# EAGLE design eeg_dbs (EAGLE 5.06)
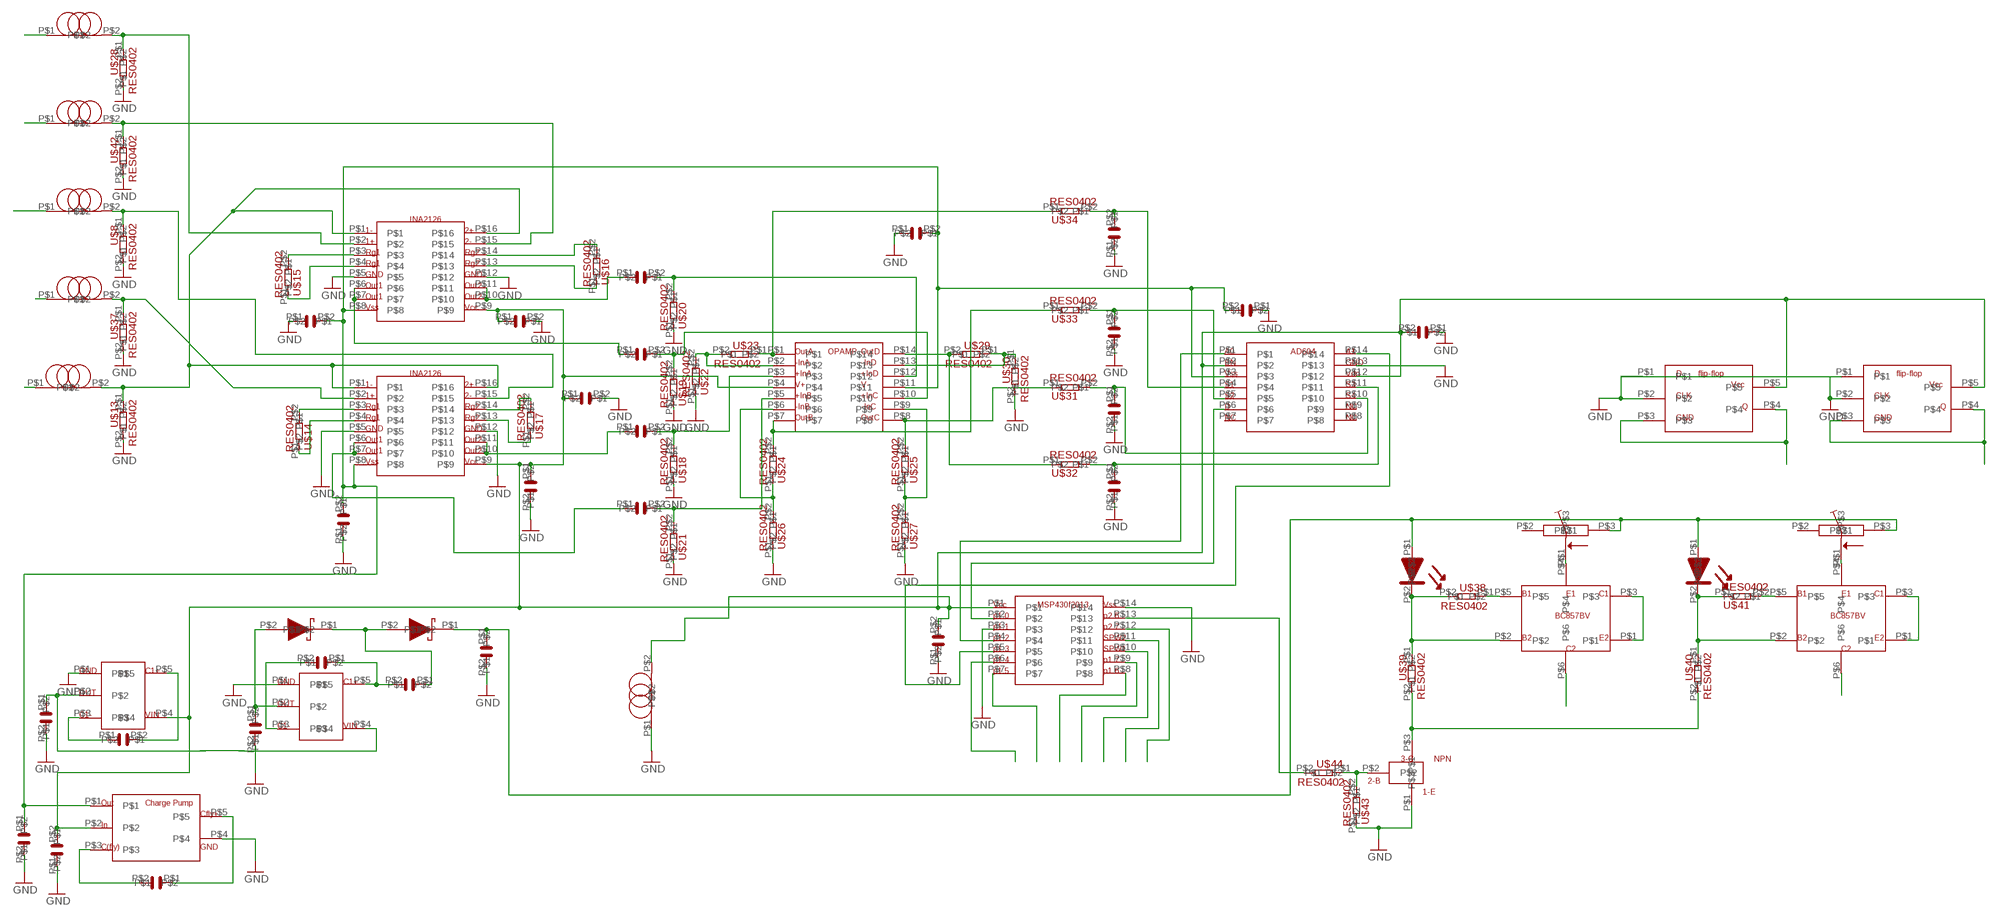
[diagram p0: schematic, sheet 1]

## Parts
U$1  BC857BV  [SOT-666]
U$2  BC857BV  [SOT-666]
U$5  FLIPFLOP  [SC70-5]
U$6  INSTAMP  [SOIC-16]
U$7  INSTAMP  [SOIC-16]
U$8  RES0402  [0402]
U$9  MSP430F2013  [TSSOP-14]
U$10  MULTIPLEXER  [TSSOP-14]
U$11  NPN  [SOT-523]
U$12  OPAMP  [TSSOP-14]
U$13  RES0402  [0402]
U$14  RES0402  [0402]
U$15  RES0402  [0402]
U$16  RES0402  [0402]
U$17  RES0402  [0402]
U$18  RES0402  [0402]
U$19  RES0402  [0402]
U$20  RES0402  [0402]
U$21  RES0402  [0402]
U$22  RES0402  [0402]
U$23  RES0402  [0402]
U$24  RES0402  [0402]
U$25  RES0402  [0402]
U$26  RES0402  [0402]
U$27  RES0402  [0402]
U$28  RES0402  [0402]
U$29  RES0402  [0402]
U$30  RES0402  [0402]
U$31  RES0402  [0402]
U$32  RES0402  [0402]
U$33  RES0402  [0402]
U$34  RES0402  [0402]
U$35  CAP0402  [0402]
U$36  CAP0402  [0402]
U$37  RES0402  [0402]
U$38  RES0402  [0402]
U$39  RES0402  [0402]
U$40  RES0402  [0402]
U$41  RES0402  [0402]
U$42  RES0402  [0402]
U$43  RES0402  [0402]
U$44  RES0402  [0402]
U$45  CAP0402  [0402]
U$46  CAP0402  [0402]
U$47  CAP0402  [0402]
U$48  CHARGEPUMP  [SOT-23]
U$49  CAP0402  [0402]
U$50  MAX1683  [SOT-23]
U$51  MAX1683  [SOT-23]
U$52  IND0603  [0603]
U$53  CAP0402  [0402]
U$54  CAP0402  [0402]
U$55  CAP0402  [0402]
U$56  CAP0402  [0402]
U$57  CAP0402  [0402]
U$58  CAP0402  [0402]
U$59  CAP0402  [0402]
U$60  CAP0402  [0402]
U$61  CAP0402  [0402]
U$62  CAP0402  [0402]
U$63  CAP0402  [0402]
U$64  CAP0402  [0402]
U$65  CAP0402  [0402]
U$66  CAP0402  [0402]
U$67  CAP0402  [0402]
U$68  CAP0402  [0402]
U$69  LED  [0402]
U$70  LED  [0402]
U$72  CAP0402  [0402]
U$73  CAP0402  [0402]
U$74  DIODE  [S0D-923]
U$75  DIODE  [S0D-923]
U$76  CAP0402  [0402]
U$77  CAP0402  [0402]
U$78  IND0603  [0603]
U$79  IND0603  [0603]
U$80  IND0603  [0603]
U$81  IND0603  [0603]
U$82  IND0603  [0603]
U$83  FLIPFLOP  [SC70-5]
U$84  TRIMMER2MM  [TRIM-MC]
U$85  TRIMMER2MM  [TRIM-MC]

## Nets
GND: U$5.P$1 U$5.P$2 U$6.P$5 U$6.P$12 U$7.P$5 U$7.P$12 U$8.P$2 U$9.P$3 U$9.P$14 U$10.P$13 U$11.P$1 U$13.P$2 U$18.P$1 U$19.P$1 U$20.P$1 U$21.P$1 U$22.P$1 U$26.P$1 U$27.P$1 U$28.P$2 U$30.P$2 U$36.P$1 U$37.P$2 U$42.P$2 U$43.P$1 U$45.P$1 U$46.P$2 U$47.P$1 U$48.P$4 U$49.P$2 U$50.P$1 U$51.P$1 U$52.P$1 U$57.P$1 U$58.P$1 U$59.P$1 U$60.P$1 U$61.P$2 U$62.P$2 U$63.P$2 U$64.P$1 U$65.P$2 U$66.P$2 U$68.P$2 U$73.P$2 U$77.P$2 U$83.P$1 U$83.P$2
N$1: U$6.P$1 U$6.P$16 U$7.P$1 U$7.P$16 U$13.P$1 U$78.P$2
N$2: U$6.P$2 U$28.P$1 U$81.P$2
N$3: U$5.P$3 U$5.P$4
N$4: U$83.P$3 U$83.P$4
N$9: U$7.P$3 U$14.P$2
N$10: U$7.P$4 U$14.P$1
N$11: U$7.P$13 U$17.P$1
N$12: U$7.P$14 U$17.P$2
N$13: U$6.P$3 U$15.P$2
N$14: U$7.P$10 U$7.P$11 U$55.P$1
N$17: U$6.P$14 U$16.P$2
N$19: U$6.P$4 U$15.P$1
N$20: U$12.P$10 U$19.P$2 U$54.P$2
N$21: U$6.P$13 U$16.P$1
N$22: U$5.P$5 U$6.P$9 U$7.P$9 U$9.P$1 U$10.P$2 U$10.P$12 U$12.P$4 U$36.P$2 U$46.P$1 U$48.P$2 U$49.P$1 U$50.P$4 U$52.P$2 U$57.P$2 U$64.P$2 U$68.P$1 U$83.P$5
N$24: U$81.P$1
N$25: U$6.P$10 U$6.P$11 U$53.P$1
N$26: U$82.P$1
N$27: U$6.P$6 U$6.P$7 U$54.P$1
N$28: U$12.P$12 U$20.P$2 U$53.P$2
N$29: U$12.P$1 U$23.P$1 U$34.P$1
N$30: U$35.P$2 U$48.P$3
N$31: U$12.P$5 U$21.P$2 U$56.P$2
N$32: U$7.P$6 U$7.P$7 U$56.P$1
N$33: U$12.P$2 U$22.P$2 U$23.P$2
N$34: U$12.P$7 U$24.P$2 U$33.P$1
N$35: U$12.P$6 U$24.P$1 U$26.P$2
N$36: U$10.P$10 U$31.P$2 U$62.P$1
N$37: U$12.P$8 U$25.P$2 U$31.P$1
N$38: U$12.P$9 U$25.P$1 U$27.P$2
N$39: U$12.P$14 U$29.P$2 U$32.P$1
N$40: U$12.P$13 U$29.P$1 U$30.P$1
N$42: U$6.P$15 U$42.P$1 U$80.P$2
N$43: U$10.P$11 U$32.P$2 U$63.P$1
N$44: U$9.P$2 U$10.P$6
N$45: U$9.P$4 U$10.P$1
N$46: U$9.P$5 U$10.P$14
N$47: U$12.P$3 U$18.P$2 U$55.P$2
N$48: U$35.P$1 U$48.P$5
N$49: U$9.P$6
N$50: U$9.P$7
N$51: U$9.P$8
N$52: U$9.P$9
N$53: U$9.P$10
N$54: U$9.P$11
N$55: U$9.P$12
N$56: U$50.P$3 U$67.P$1
N$57: U$50.P$5 U$67.P$2
N$58: U$2.P$2 U$38.P$2 U$39.P$1 U$69.P$2
N$59: U$2.P$5 U$38.P$1
N$60: U$2.P$4 U$84.P$1
N$61: U$11.P$3 U$39.P$2 U$40.P$2
N$62: U$2.P$6
N$63: U$2.P$1 U$2.P$3
N$64: U$1.P$4 U$85.P$1
N$65: U$1.P$2 U$40.P$1 U$41.P$1 U$70.P$2
N$66: U$1.P$5 U$41.P$2
N$67: U$1.P$6
N$68: U$1.P$1 U$1.P$3
N$69: U$50.P$2 U$51.P$4 U$66.P$1
N$70: U$11.P$2 U$43.P$2 U$44.P$1
N$71: U$51.P$3 U$72.P$2
N$72: U$9.P$13 U$44.P$2
N$73: U$6.P$8 U$7.P$8 U$10.P$3 U$12.P$11 U$45.P$2 U$47.P$2 U$48.P$1 U$58.P$2 U$60.P$2 U$65.P$1
N$74: U$51.P$5 U$72.P$1 U$76.P$2
N$75: U$51.P$2 U$73.P$1 U$74.P$2
N$76: U$74.P$1 U$75.P$2 U$76.P$1
N$77: U$69.P$1 U$70.P$1 U$75.P$1 U$77.P$1 U$84.P$3 U$85.P$3
N$78: U$10.P$4 U$34.P$2 U$59.P$2
N$82: U$10.P$5 U$33.P$2 U$61.P$1
N$83: U$7.P$15 U$8.P$1 U$82.P$2
N$84: U$80.P$1
N$85: U$7.P$2 U$37.P$1 U$79.P$2
N$86: U$79.P$1
N$89: U$78.P$1
Unconnected: U$10.P$7 U$10.P$8 U$10.P$9 U$84.P$2 U$85.P$2

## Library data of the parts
U$1 U$2 = my project parts:BC857BV
U$5 U$83 = my project parts:FLIPFLOP
U$6 U$7 = my project parts:INSTAMP
U$8 U$13-U$34 U$37-U$44 = my project parts:RES0402
U$9 = my project parts:MSP430F2013
U$10 = my project parts:MULTIPLEXER
U$11 = my project parts:NPN
U$12 = my project parts:OPAMP
U$35 U$36 U$45-U$47 U$49 U$53-U$68 U$72 U$73 U$76 U$77 = my project parts:CAP0402
U$48 = my project parts:CHARGEPUMP
U$50 U$51 = my project parts:MAX1683
U$52 U$78-U$82 = my project parts:IND0603
U$69 U$70 = my project parts:LED
U$74 U$75 = my project parts:DIODE
U$84 U$85 = my project parts:TRIMMER2MM

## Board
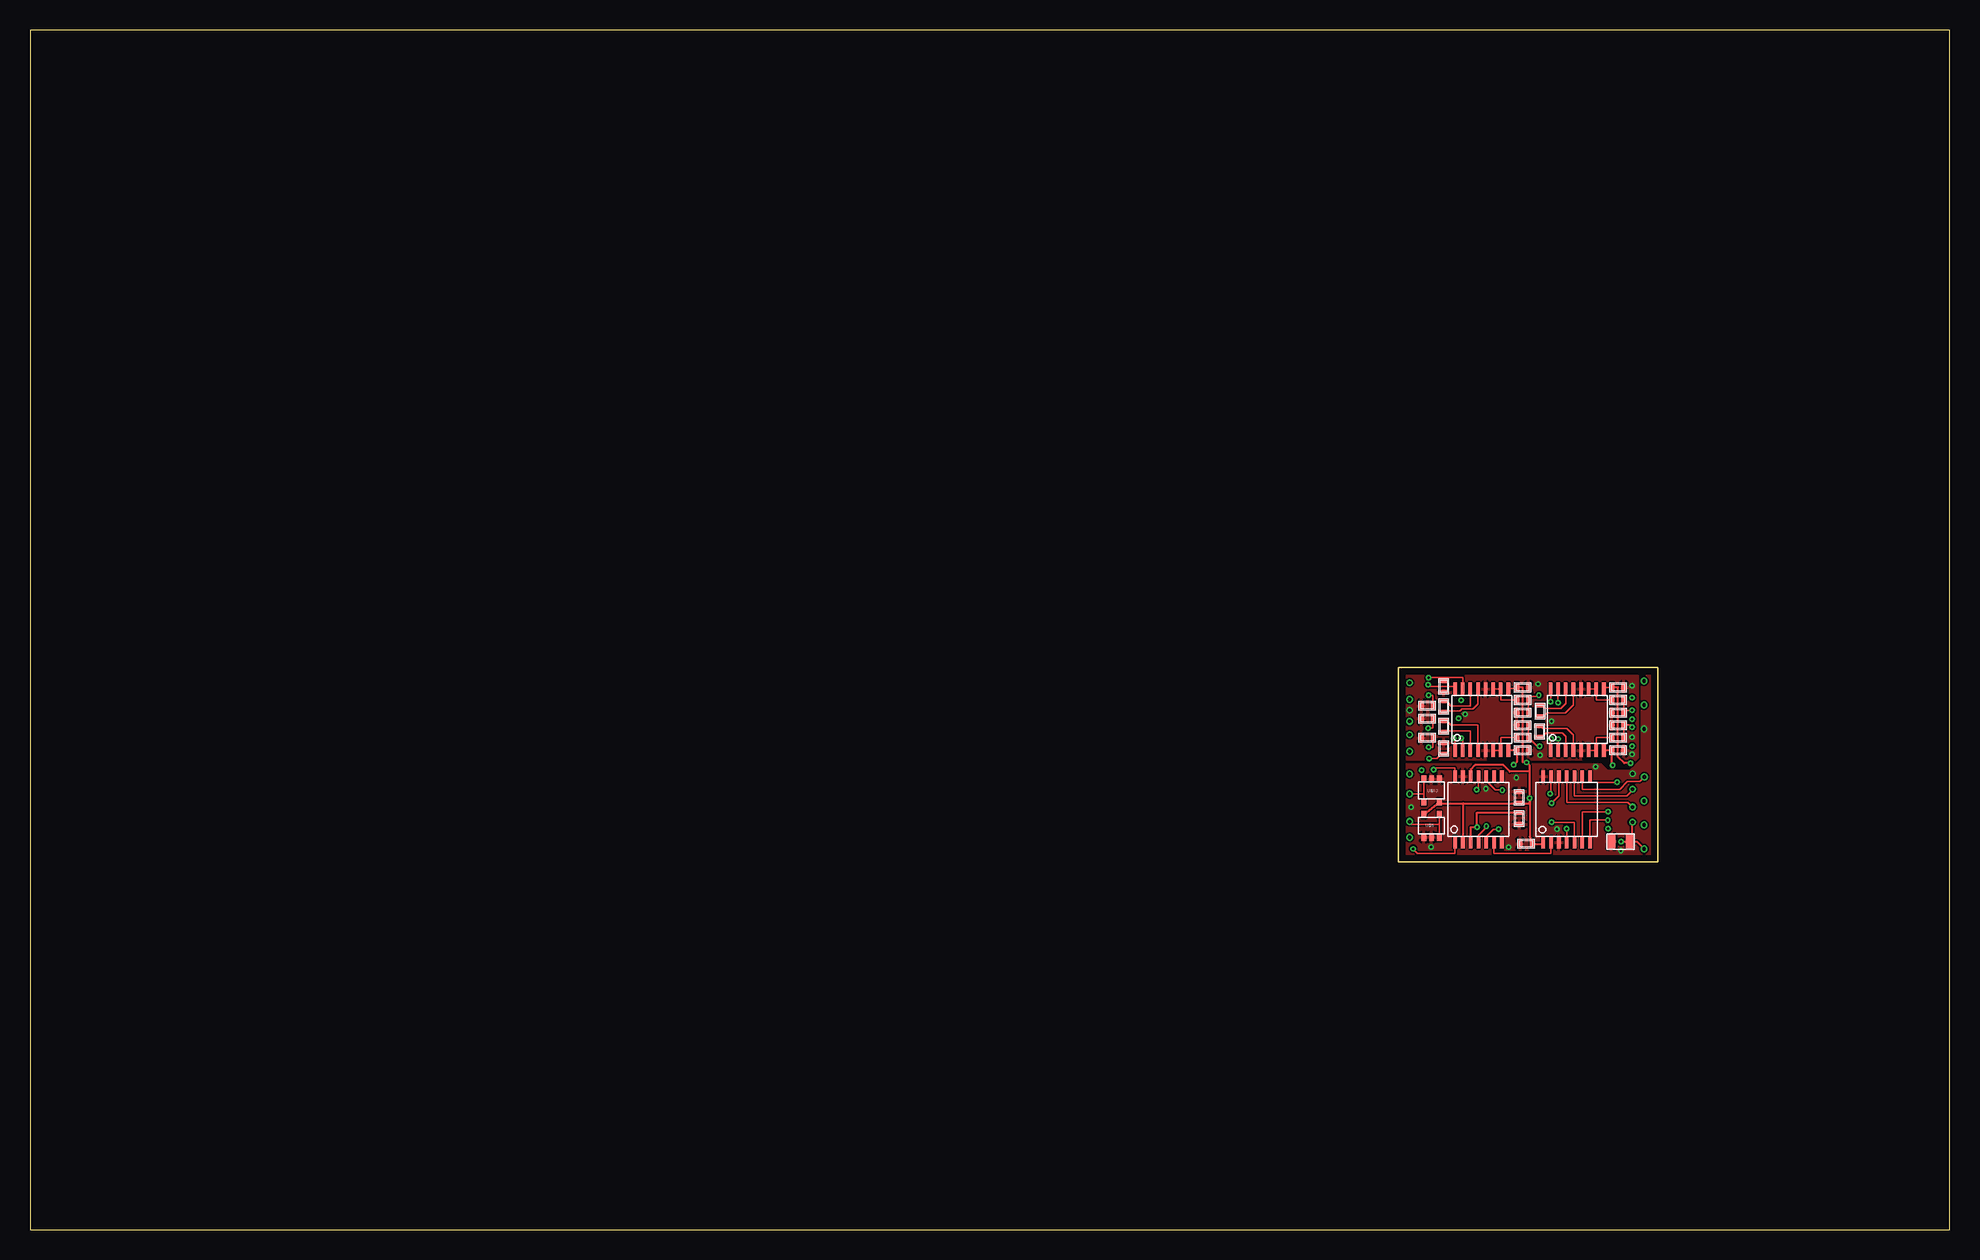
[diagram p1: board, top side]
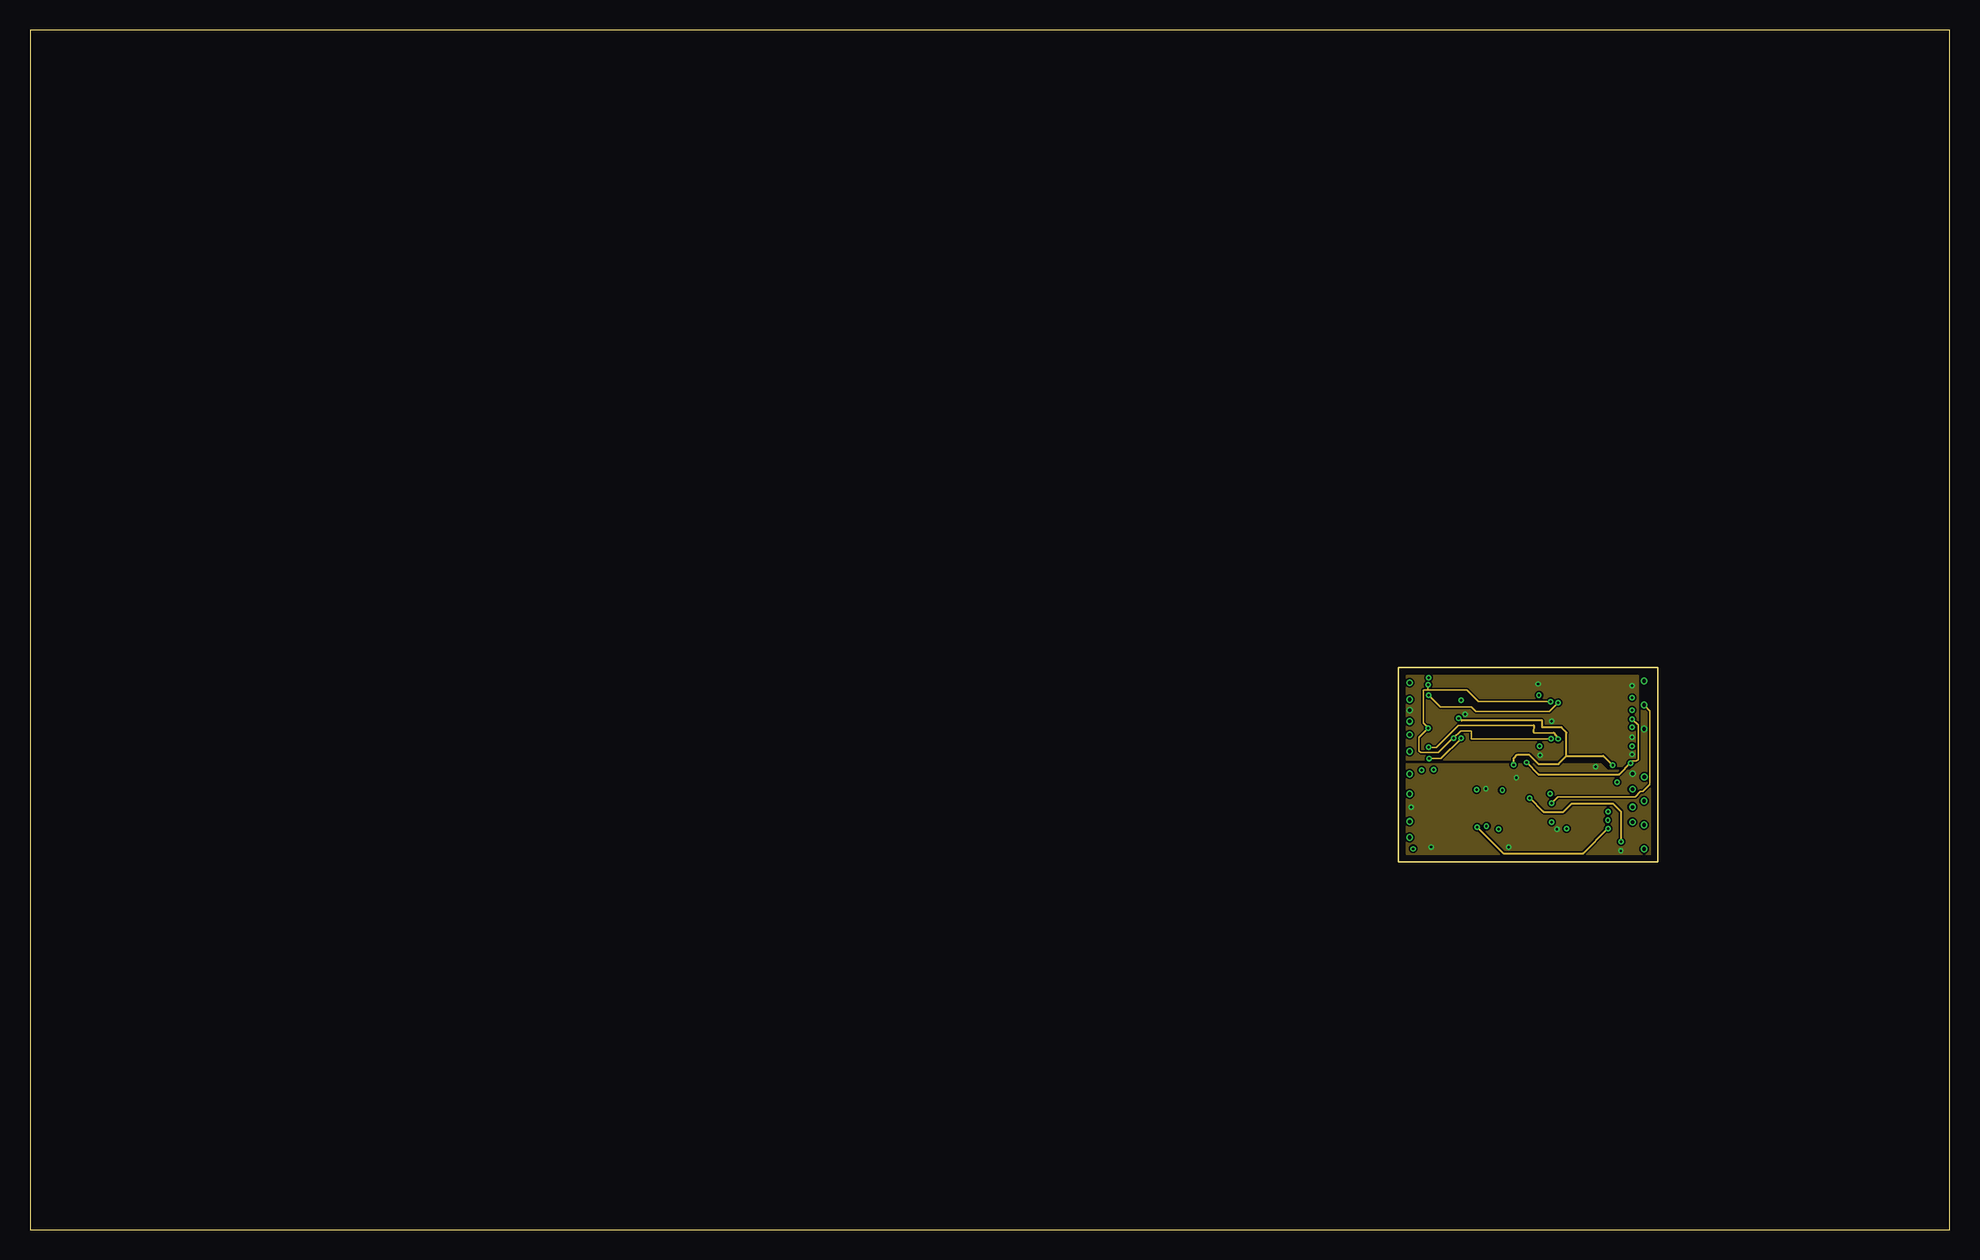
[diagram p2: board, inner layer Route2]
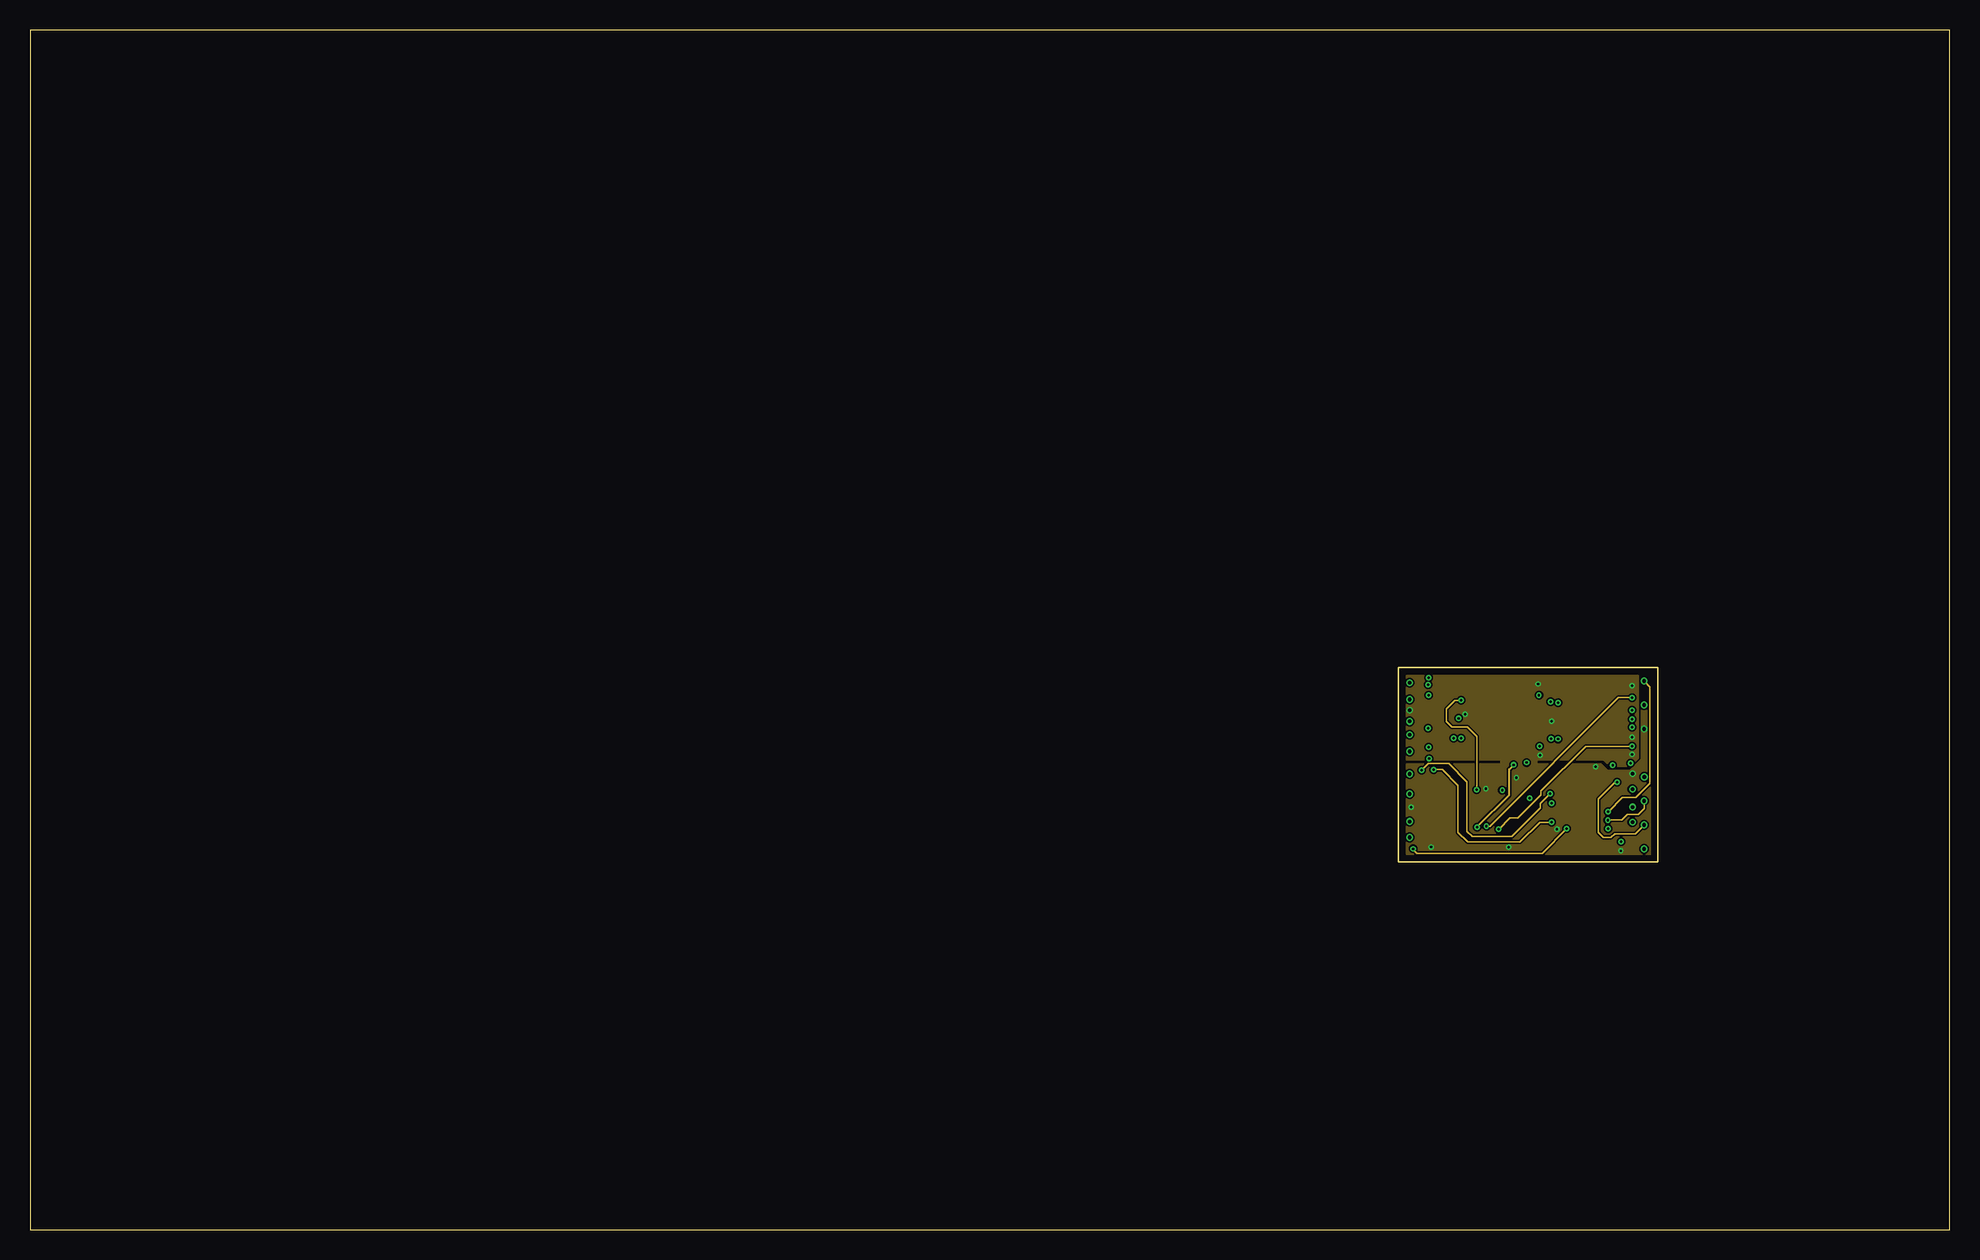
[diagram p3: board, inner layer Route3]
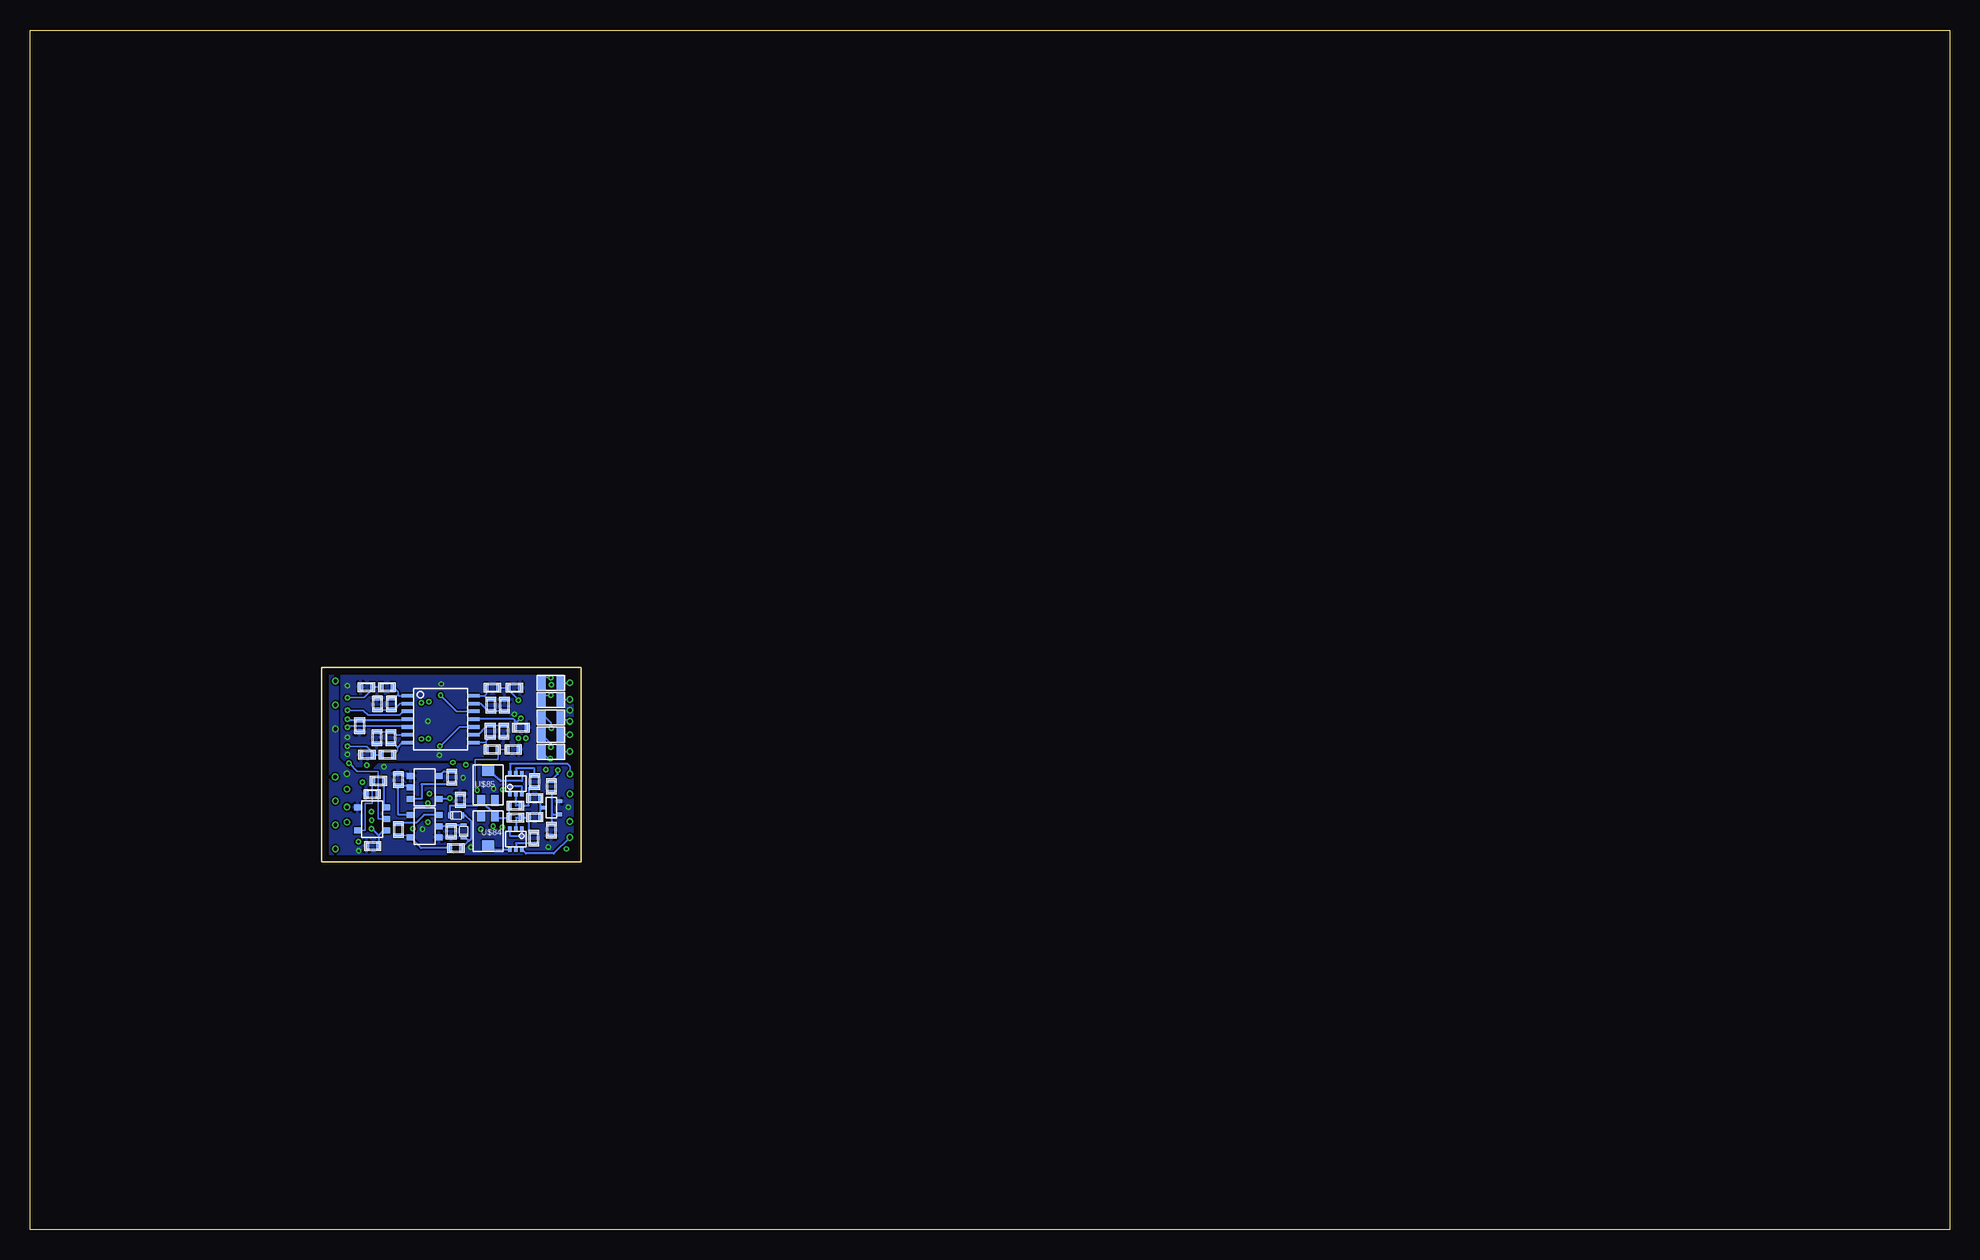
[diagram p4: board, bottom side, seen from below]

Size 160 x 100 mm. Coordinates in mm from the lower left corner, seen from the top.
Outline: 0,0 160,0 160,100 0,100 0,0
Outline: 135.7,46.85 135.7,30.63 114.07,30.63 114.07,46.85 135.7,46.85
Copper layers (1+2*3+16): Top 0.035mm / dielectric 0.38mm / Route2 0.035mm / dielectric 0.71mm / Route3 0.035mm / dielectric 0.38mm / Bottom 0.035mm
Design rules "default *": minimum track width 0.125mm, minimum drill 0.2mm, track to track 5mil, track to pad 6mil, pad to pad 6mil, via to via 5mil, smd to smd 6mil, copper to edge 0.5mm, drill to drill 8mil, minimum pad ring 10mil, minimum via ring 5mil, stop-mask expansion 3mil, vias tented up to drill 8mil, thermal gap 0.2mm

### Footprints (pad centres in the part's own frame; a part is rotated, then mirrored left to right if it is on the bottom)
SOT-666 = smd 0.3 x 0.4: P$1 -0.5,-0.85; P$2 0,-0.85; P$3 0.5,-0.85; P$4 0.5,0.85; P$5 0,0.85; P$6 -0.5,0.85
SC70-5 = smd 0.4 x 0.6: P$1 -0.65,-0.95; P$2 0,-0.95; P$3 0.65,-0.95; P$4 0.65,0.95; P$5 -0.65,0.95
SOIC-16 = smd 0.3 x 1.1: P$1 -2.223,-2.55; P$2 -1.587,-2.55; P$3 -0.953,-2.55; P$4 -0.318,-2.55; P$5 0.318,-2.55; P$6 0.953,-2.55; P$7 1.587,-2.55; P$8 2.223,-2.55; P$9 2.223,2.55; P$10 1.587,2.55; P$11 0.953,2.55; P$12 0.318,2.55; P$13 -0.318,2.55; P$14 -0.953,2.55; P$15 -1.587,2.55; P$16 -2.223,2.55
0402 = smd 0.381 x 0.8: P$1 -0.49,0; P$2 0.49,0
TSSOP-14 = smd 0.3 x 1: P$1 -1.95,-2.75; P$2 -1.3,-2.75; P$3 -0.65,-2.75; P$4 0,-2.75; P$5 0.65,-2.75; P$6 1.3,-2.75; P$7 1.95,-2.75; P$8 1.95,2.75; P$9 1.3,2.75; P$10 0.65,2.75; P$11 0,2.75; P$12 -0.65,2.75; P$13 -1.3,2.75; P$14 -1.95,2.75
SOT-523 = smd 0.3 x 0.45: P$1 0.55,-0.65; P$2 -0.55,-0.65; P$3 0,0.65
SOT-23 = smd 0.5 x 0.625: P$1 -0.95,-1.188; P$2 0,-1.188; P$3 0.95,-1.188; P$4 0.95,1.188; P$5 -0.95,1.188
0603 = smd 0.629 x 1.138: P$1 -0.764,0; P$2 0.764,0
S0D-923 = smd 0.25 x 0.5: P$1 -0.53,0; P$2 0.53,0
TRIM-MC = smd 1 x 0.9: P$1 0,1.25 | smd 0.65 x 0.9: P$2 0.575,-1.25; P$3 -0.575,-1.25

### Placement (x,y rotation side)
U$1  119.49,37.17 0 bottom
U$2  119.49,32.54 180 bottom
U$5  116.83,33.66 0 top
U$6  121.01,42.5 0 top
U$7  128.96,42.5 0 top
U$8  116.47,43.66 180 top
U$9  128.09,35.01 0 top
U$10  120.74,35.03 0 top
U$11  116.53,35.15 90 bottom
U$12  125.79,42.55 270 bottom
U$13  116.47,42.59 180 top
U$14  125.85,41.52 270 top
U$15  117.85,41.95 270 top
U$16  117.85,43.6 90 top
U$17  125.86,43.22 90 top
U$18  132.37,43.09 0 top
U$19  124.42,42.05 0 top
U$20  124.42,43.09 0 top
U$21  132.37,42.05 0 top
U$22  131.05,43.82 270 bottom
U$23  129.86,43.82 270 bottom
U$24  129.93,41 270 bottom
U$25  121.64,41.54 270 bottom
U$26  131.09,41 90 bottom
U$27  120.51,41.54 90 bottom
U$28  117.85,40.11 90 top
U$29  121.59,43.7 90 bottom
U$30  120.45,43.7 90 bottom
U$31  121.48,40.02 0 bottom
U$32  121.46,45.15 0 bottom
U$33  130.21,39.58 180 bottom
U$34  130.24,45.22 180 bottom
U$35  130.95,37.39 0 bottom
U$36  131.48,36.31 0 bottom
U$37  116.47,41 180 top
U$38  118,32.63 90 bottom
U$39  117.93,34.36 0 bottom
U$40  117.93,35.95 0 bottom
U$41  117.94,37.33 90 bottom
U$42  117.85,45.28 270 top
U$43  116.55,33.3 90 bottom
U$44  116.55,36.94 90 bottom
U$45  124.42,39.95 180 top
U$46  124.42,45.19 0 top
U$47  132.37,39.95 180 top
U$48  131.49,34.22 90 bottom
U$49  132.37,45.19 0 top
U$50  127.09,36.86 270 bottom
U$51  127.09,33.62 90 bottom
U$52  132.59,32.34 0 top
U$53  124.42,44.14 0 top
U$54  124.42,41 0 top
U$55  132.37,44.14 0 top
U$56  132.37,41 0 top
U$57  124.7,32.16 0 top
U$58  119.08,41.85 180 bottom
U$59  131.95,45.22 0 bottom
U$60  124.13,34.26 90 top
U$61  131.91,39.58 180 bottom
U$62  119.73,40.02 0 bottom
U$63  119.63,45.15 0 bottom
U$64  124.13,36.02 270 top
U$65  131.43,31.96 180 bottom
U$66  129.3,37.49 90 bottom
U$67  124.84,37.71 90 bottom
U$68  132.52,41.99 270 bottom
U$69  119.56,34.32 0 bottom
U$70  119.56,35.35 0 bottom
U$72  129.3,33.33 90 bottom
U$73  124.89,33.19 270 bottom
U$74  123.86,33.2 90 bottom
U$75  124.48,34.52 0 bottom
U$76  124.51,31.8 180 bottom
U$77  124.13,35.81 90 bottom
U$78  116.57,42.7 180 bottom
U$79  116.57,41.26 180 bottom
U$80  116.57,45.58 180 bottom
U$81  116.57,39.81 180 bottom
U$82  116.57,44.15 180 bottom
U$83  116.83,36.6 180 top
U$84  121.82,33.23 180 bottom
U$85  121.82,37.03 0 bottom

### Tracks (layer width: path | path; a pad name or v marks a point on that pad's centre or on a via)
GND  (via drill 0.2, 0.3)
  other vias: 119.64,42.97 126.84,42.38 133.56,39.61 133.56,45.34 125.87,39.53 125.71,45.48 133.56,41.04 134.54,41.73 127.27,33.38 121.35,36.74 123.9,37.66 133.57,37.99 115.13,35.2 114.99,43.28 123.26,31.86 116.79,31.89 130.5,38.57 132.61,31.57
  pour Top: 135.16,31.29 114.74,31.29 114.74,38.85 130.94,38.81 131.49,38.26 133.41,38.26 134.33,39.18 134.33,46.19 135.16,46.19
  pour Bottom: 135.16,31.29 114.74,31.29 114.74,38.81 130.94,38.81 131.49,38.26 133.41,38.26 134.33,39.18 134.33,46.19 135.16,46.19
  pour Route2: 114.74,46.19 134.04,46.19 134.04,39.33 133.3,38.59 131.75,38.59 131.2,39.14 114.74,39.14
  pour Route2: 135.16,31.29 114.74,31.29 114.74,38.84 130.94,38.81 131.49,38.26 133.41,38.26 134.33,39.18 134.33,46.19 135.16,46.19
  pour Top: 114.74,46.19 134.04,46.19 134.04,39.33 133.3,38.59 131.75,38.59 131.2,39.14 114.74,39.14
  pour Route3: 135.16,31.29 114.74,31.29 114.74,38.83 122.6,38.81 122.6,39.14 114.74,39.14 114.74,46.19 134.04,46.19 134.04,39.33 133.3,38.59 131.75,38.59 131.2,39.14 125.6,39.14 125.6,38.81 130.94,38.81 131.49,38.26 133.41,38.26 134.33,39.18 134.33,46.19 135.16,46.19
  pour Bottom: 134.04,46.19 134.04,39.33 133.3,38.59 131.75,38.59 131.2,39.14 117.9,39.14 117.85,46.19
  pour Bottom: 114.74,46.19 117.08,46.19 117.08,39.14 114.74,39.14
N$1  (via drill 0.2)
  Top 0.125: 118.76,45.27 U$6.P$16 118.79,45.28 116.73,45.28 v116.53,45.41 | U$13.P$1 116.96,41.79 v116.56,41.79 | v118.67,40.96 118.79,40.84 U$6.P$1 | v126.75,44 126.75,45.04 U$7.P$16 | v126.79,40.91 126.74,40.86 U$7.P$1
  Route2 0.125: 116.53,44.96 119.78,44.96 120.74,44 v126.75,44 | v126.79,40.91 120.14,40.91 120.14,41.58 119.28,41.58 v118.67,40.96 118.6,40.96 117.39,39.76 115.92,39.76 115.78,39.9 115.78,41.02 116.53,41.77 v116.56,41.79 116.14,42.21 116.14,44.96 116.53,44.96 | 116.53,44.96 v116.53,45.41
  Bottom 0.125: v116.56,41.79 116.56,42.25 117.01,42.7 U$78.P$2
N$2  (via drill 0.2)
  Top 0.125: 117.93,39.49 U$28.P$1 117.62,39.62 117.27,39.27 v116.62,39.27 | 119.5,39.93 119.44,39.93 arc-90 U$6.P$2 119.42,40.83 v119.29,40.96
  Route2 0.125: v119.29,40.96 117.6,39.27 v116.62,39.27
  Bottom 0.125: U$81.P$2 116.81,39.27 v116.62,39.27
N$3  (via drill 0.3)
  Top 0.125: 117.48,33.77 U$5.P$4 | U$5.P$3 117.48,33.77 | v114.99,34.02 115.06,33.77 117.48,33.77
N$4  (via drill 0.3)
  Top 0.125: U$83.P$3 116.18,36.17 | 116.18,36.17 U$83.P$4 | v114.99,36.31 116.18,36.31 116.18,36.17
N$9
  Top 0.125: U$7.P$3 128.01,41.11 127.73,41.39 126.4,41.39 126.04,41.03 U$14.P$2
N$10
  Top 0.125: 126,41.95 125.97,42.07 U$14.P$1 126.08,41.78 128.1,41.78 128.64,41.23 U$7.P$4
N$11
  Top 0.125: 126,42.84 126.02,42.71 125.58,42.78 U$17.P$1 126.1,42.73 126.43,43.06 128,43.06 128.64,43.71 U$7.P$13
  Top 0.15: U$17.P$1 125.53,42.71
N$12
  Top 0.125: U$17.P$2 126.15,43.61 126.31,43.45 127.6,43.45 128.01,43.85 U$7.P$14
N$13
  Top 0.125: U$15.P$2 117.91,41.51 117.57,41.39 117.98,41.56 120.06,41.56 U$6.P$3
N$14
  Top 0.125: U$7.P$11 U$7.P$10 130.55,44.14 U$55.P$1
N$17
  Top 0.125: U$6.P$14 120.06,43.66 118.44,43.66 118.08,44.09 U$16.P$2
N$19
  Top 0.125: U$6.P$4 120.69,42.06 118.44,42.06 118.06,42.44 U$15.P$1
N$20  (via drill 0.2)
  Top 0.125: v125.83,40.28 125.64,40.28 U$54.P$2 U$19.P$2
  Bottom 0.125: U$12.P$10 124.21,41.9 v125.83,40.28
N$21
  Top 0.125: U$16.P$1 117.55,43.23 119.17,43.23 119.34,43.4 120.28,43.4 120.69,43.82 U$6.P$13
N$22  (via drill 0.2, 0.3)
  Top 0.125: U$7.P$9 131.17,45.15 131.21,45.19 U$49.P$1 | U$10.P$12 | 123.17,45.11 123.93,45.11 U$46.P$1
  Top 0.15: 123.17,45.11 U$6.P$9 | U$46.P$1 124.43,45.19 124.43,38.95 124.74,38.95 v124.75,38.94 125.01,38.68 125.01,38.19 | v125.01,35.98 125.01,38.19 | U$49.P$1 132.37,45.19 132.37,39.38 132.88,38.88 v133.41,38.88 | 117.6,35.53 U$64.P$2 125.01,35.53 v125.01,35.98 | 117.6,35.53 U$83.P$5 U$5.P$5 | 117.6,35.53 119.44,35.53 U$10.P$2 | U$9.P$1 126.14,32.16 U$57.P$2 125.01,32.73 v125.01,35.98 | v132.61,32.33 v132.62,32.34 U$52.P$2 | U$52.P$2 133.93,32.34 v134.54,31.73 | v133.57,33.97 133.57,32.55 U$52.P$2 | U$10.P$12 120.09,38.36 120.45,38.71 122.81,38.71 123.33,38.19 125.01,38.19
  Route2 0.125: v133.41,38.88 133.58,39.05 133.91,39.05 134.05,39.19 134.05,42.05 v133.56,42.54
  Route2 0.15: v125.01,35.98 126.17,34.82 127.82,34.82 128.51,35.51 131.96,35.51 132.61,34.85 v132.61,32.33 | v133.41,38.88 132.47,37.94 125.75,37.94 v124.75,38.94
  Bottom 0.125: v133.41,38.88 132.72,38.19 130.96,38.19 130.96,36.34 U$36.P$2 130.99,34.22 U$48.P$2
  Bottom 0.15: U$36.P$2 130.95,36.35 | v133.56,42.54 133.5,42.48 U$68.P$1 128.61,42.48 U$12.P$4 | v125.01,35.98 125.07,35.91 U$50.P$4
N$24  (via drill 0.3)
  Bottom 0.15: U$81.P$1 v114.99,39.85
N$25
  Top 0.125: U$6.P$11 U$6.P$10 122.6,44.14 U$53.P$1
N$26  (via drill 0.3)
  Bottom 0.15: U$82.P$1 v114.99,44.19
N$27
  Top 0.125: U$6.P$6 U$6.P$7 122.6,41 U$54.P$1
N$28  (via drill 0.2)
  Top 0.125: U$20.P$2 U$53.P$2 124.92,44.45 125.68,44.45 v125.77,44.53
  Top 0.15: U$20.P$2 124.82,42.94 | U$53.P$2 124.98,44.04
  Bottom 0.125: U$12.P$12 124.44,43.2 v125.77,44.53
N$29
  Bottom 0.125: 129.33,44.59 129.6,44.31 U$23.P$1 | U$34.P$1 129.33,44.8 129.33,44.59 | U$12.P$1 129.24,44.5 129.33,44.59
N$30
  Bottom 0.15: U$35.P$2 130.46,35.33 arc-90 U$48.P$3
N$31  (via drill 0.2)
  Top 0.125: U$56.P$2 132.88,40.89 132.88,42.03 U$21.P$2 133.39,42.05 v133.56,41.88
  Bottom 0.125: U$12.P$5 128.76,41.98 133.45,41.98 v133.56,41.88
N$32
  Top 0.125: U$7.P$6 U$7.P$7 130.55,41 U$56.P$1
N$33
  Bottom 0.125: U$22.P$2 U$23.P$2 129.65,43.33 129.13,43.85 U$12.P$2
N$34
  Bottom 0.125: 129.72,40.41 U$24.P$2 129.69,40.51 129.37,40.2 | U$33.P$1 129.37,39.93 129.37,40.2 | 129.37,40.2 128.97,40.6 U$12.P$7
N$35
  Bottom 0.125: U$12.P$6 129.44,41.25 129.68,41.49 U$24.P$1 U$26.P$2
N$36  (via drill 0.2)
  Top 0.125: U$10.P$10 121.39,37.4 122.16,36.63 v122.73,36.63
  Bottom 0.125: U$31.P$2 120.9,40.01 | U$31.P$2 120.86,39.96 | U$31.P$2 U$62.P$1 | U$31.P$2 120.99,39.18 122.89,39.18 122.89,36.8 v122.73,36.63
N$37
  Bottom 0.125: U$25.P$2 121.97,40.72 121.97,40.59 | U$31.P$1 121.97,40.59 | U$12.P$8 121.97,40.59
N$38
  Bottom 0.125: U$27.P$2 U$25.P$1 121.81,41.92 121.98,41.92 122.66,41.25 U$12.P$9
N$39
  Bottom 0.125: 121.85,44.31 U$29.P$2 121.82,44.19 122.12,44.5 | 122.12,44.5 U$12.P$14 | U$32.P$1 121.95,44.67 122.12,44.5
N$40
  Bottom 0.125: U$12.P$13 122.44,43.85 121.8,43.21 U$29.P$1 U$30.P$1
N$42  (via drill 0.2)
  Top 0.125: v116.59,46.01 117.86,46.01 | 117.86,46.01 119.42,46.01 U$6.P$15 | U$42.P$1 117.86,45.77 117.86,46.01
  Bottom 0.125: v116.59,46.01 117.33,46.01 U$80.P$2
N$43  (via drill 0.2)
  Top 0.125: U$10.P$11 120.74,36.82 v120.58,36.66
  Route3 0.125: v120.58,36.66 120.58,41.1 119.81,41.88 118.52,41.88 118.05,42.35 118.05,43.38 118.78,44.11 v119.28,44.11
  Bottom 0.125: U$32.P$2 U$63.P$1 120.12,45.01 v119.28,44.11
N$44
  Top 0.125: U$10.P$6 122.04,31.36 126.79,31.36 U$9.P$2
N$45  (via drill 0.2)
  Top 0.125: U$10.P$1 118.79,31.36 115.65,31.36 v115.28,31.73 | v128.08,33.42 U$9.P$4
  Route3 0.125: v128.08,33.42 126.06,31.36 115.62,31.36 v115.28,31.73
N$46  (via drill 0.2)
  Top 0.125: U$10.P$14 118.79,38.46 117.11,38.46 v117,38.34 | v126.83,33.95 128.74,33.95 U$9.P$5
  Route3 0.125: v117,38.34 117.72,38.34 119.04,37.03 119.04,33.09 119.84,32.3 124.21,32.3 125.86,33.95 v126.83,33.95
N$47  (via drill 0.2)
  Top 0.125: v133.55,43.28 132.86,43.28 U$18.P$2 U$55.P$2
  Bottom 0.125: U$12.P$3 128.9,43.2 129.21,42.9 131.82,42.9 132.21,43.28 v133.55,43.28
N$48
  Bottom 0.125: U$48.P$5 132.07,33.27 132.07,35.5 131.5,35.5 131.5,37.34 U$35.P$1
N$49  (via drill 0.2, 0.3)
  Top 0.125: U$9.P$6 129.39,34.83 v131.55,34.83
  Route3 0.125: v131.55,34.83 132.75,36.03 133.86,36.03 135.03,37.2 135.03,45.24 v134.54,45.73
N$50  (via drill 0.2, 0.3)
  Top 0.125: v131.52,34.14 130.04,34.14 U$9.P$7
  Route3 0.125: v131.52,34.14 132.67,34.14 133.14,34.61 134.05,34.61 134.54,35.1 v134.54,35.73
N$51  (via drill 0.2, 0.3)
  Top 0.125: v132.28,37.29 130.04,37.29 U$9.P$8
  Top 0.15: U$9.P$8 130.04,37.83
  Route3 0.125: v134.54,33.73 133.8,32.98 132.09,32.98 131.78,32.67 131.16,32.67 130.72,33.11 130.72,35.89 132.12,37.29 v132.28,37.29
N$52  (via drill 0.3)
  Top 0.125: U$9.P$9 129.39,36.71 132.54,36.71 133.17,37.34 134.17,37.34 v134.56,37.73
N$53  (via drill 0.3)
  Top 0.125: U$9.P$10 128.74,36.14 133.11,36.14 133.57,36.6 v133.57,36.71
N$54  (via drill 0.3)
  Top 0.125: U$9.P$11 128.09,35.59 133.2,35.59 v133.57,35.22
N$55  (via drill 0.2, 0.3)
  Top 0.125: U$9.P$12 127.44,36.15 v126.83,35.54
  Route2 0.125: v134.54,43.73 135.03,43.24 135.03,37.1 134.44,36.51 134.23,36.51 133.8,36.08 127.37,36.08 v126.83,35.54
N$56
  Bottom 0.125: U$67.P$1 124.95,37.11
  Bottom 0.15: 124.95,37.11 127.36,37.11 127.36,35.91 U$50.P$3
N$57
  Bottom 0.15: U$67.P$2 125.51,38.2 U$50.P$5
N$58
  Bottom 0.15: U$39.P$1 118.39,34.32 | U$39.P$1 119.06,34.36 U$69.P$2 119.49,34.32 U$2.P$2 | U$38.P$2 118.42,33.12 U$39.P$1
N$59
  Bottom 0.15: U$2.P$5 119.49,32.2 118,32.2 U$38.P$1
N$60
  Bottom 0.15: U$2.P$4 121.64,31.69 U$84.P$1
N$61
  Bottom 0.15: 117.44,35.09 U$40.P$2 | U$39.P$2 117.44,35.09 | 117.44,35.09 U$11.P$3
N$62  (via drill 0.3)
  Bottom 0.15: U$2.P$6 118.65,31.34 116.34,31.34 v114.99,32.69
N$63
  Bottom 0.15: U$2.P$1 118.99,32.78 119.99,32.78 U$2.P$3
N$64
  Bottom 0.15: U$1.P$4 118.99,37.39 120.78,37.39 U$85.P$1
N$65
  Bottom 0.15: U$1.P$2 119.49,35.35 U$70.P$2 118.42,35.35 U$40.P$1 | U$40.P$1 118.37,36 | U$40.P$1 arc-90 118.4,35.97 118.4,36.84 U$41.P$1
N$66
  Bottom 0.15: U$1.P$5 119.49,38.45 117.94,38.45 U$41.P$2
N$67  (via drill 0.3)
  Bottom 0.125: 115.2,38.82 114.99,38.61 v114.99,37.98
  Bottom 0.15: U$1.P$6 119.99,38.82 115.2,38.82
N$68
  Bottom 0.15: U$1.P$3 118.99,36.93 119.99,36.93 U$1.P$1
N$69
  Bottom 0.125: U$51.P$4 128.29,34.56 | U$66.P$1 129.3,36.86
  Bottom 0.15: U$50.P$2 128.42,37 U$66.P$1 129.3,34.58 U$51.P$4
N$70
  Bottom 0.15: U$44.P$1 116.48,36.38 116.48,34.69 | 116.48,34.44 116.48,33.79 U$43.P$2 | 116.48,34.44 116.48,34.69 | 116.48,34.44 116.48,34.54 | U$11.P$2 116.48,34.6 116.48,34.69
N$71
  Bottom 0.125: U$72.P$2 129.18,33.94
  Bottom 0.15: U$51.P$3 127.15,34.58 127.82,33.9 129.3,33.9 U$72.P$2
  Bottom 0.2: U$51.P$3 125.9,34.54
N$72  (via drill 0.2)
  Top 0.125: U$9.P$13 126.79,36.41 v126.69,36.32
  Route3 0.125: v126.69,36.32 125.89,35.52 125.89,35.15 123.5,32.75 120.22,32.75 119.78,33.2 119.78,37.32 118.25,38.84 116.56,38.84 v116.01,38.3
  Bottom 0.15: v116.01,38.3 116.01,37.96 U$44.P$2
N$73  (via drill 0.2)
  Top 0.125: 131.24,39.77 U$7.P$8 | v131.93,38.7 v131.92,38.7 | U$45.P$2 | U$47.P$2 131.88,39.77
  Top 0.15: v131.92,38.7 131.88,38.74 U$47.P$2 131.24,39.95 131.24,39.77 | U$6.P$8 U$45.P$2 123.98,39.88 123.98,39.03 v123.67,38.73 | U$60.P$2 120.62,34.75 v120.62,33.55 120.09,33.55 U$10.P$3
  Route2 0.15: v131.53,33.43 129.47,31.37 122.79,31.37 v120.62,33.55 | v123.67,38.73 123.67,39.29 123.99,39.6 124.93,39.6 125.73,38.79 127.41,38.79 127.41,38.81 128.08,39.49 | v131.93,38.7 131.14,39.49 128.08,39.49 | 128.08,39.49 128.08,41.43 127.65,41.86 126.05,41.86 126.05,42.42 119.32,42.42 v119.08,42.61
  Route3 0.15: v120.62,33.55 123.3,36.22 123.3,38.35 v123.67,38.73
  Bottom 0.15: U$12.P$11 119.69,42.54 119.58,42.43 119.58,42.17 | v119.08,42.61 119.58,42.17 | 119.58,42.17 U$58.P$2 | 130.94,32.84 130.52,33.27 U$48.P$1 | v131.53,33.43 130.94,32.84 | 130.94,32.84 U$65.P$1
N$74
  Bottom 0.125: U$51.P$5 128.44,32.84 U$72.P$1
  Bottom 0.15: U$51.P$5 127.4,31.8 U$76.P$2
N$75
  Bottom 0.15: U$74.P$2 123.9,33.68 U$73.P$1 124.94,33.62 U$51.P$2 125.9,33.68
  Bottom 0.2: U$51.P$2 125.9,33.61
N$76
  Bottom 0.15: U$76.P$1 123.43,32.38 | 123.43,32.38 123.2,32.61 123.2,34.02 123.71,34.52 U$75.P$2 | U$74.P$1 123.72,32.66 123.43,32.38
N$77
  Bottom 0.15: U$70.P$1 U$69.P$1 120.98,34.32 U$84.P$3 121.25,34.63 121.98,35.29 arc17 U$85.P$3 122.4,35.64 122.71,35.32 U$77.P$1 125.01,35.32 U$75.P$1
N$78  (via drill 0.2)
  Top 0.125: U$10.P$4 120.74,32.84 121.4,33.5 v121.4,33.62
  Route3 0.125: v121.4,33.62 121.67,33.62 132.39,44.34 v133.56,44.34
  Bottom 0.125: U$34.P$2 U$59.P$2 131.46,45.04 132.16,44.34 v133.56,44.34
N$82  (via drill 0.2)
  Top 0.125: v122.43,33.37 121.97,33.37 121.39,32.79 U$10.P$5
  Route3 0.125: v133.56,40.28 129.68,40.28 125.96,36.56 125.96,36.23 124.01,34.29 123.35,34.29 v122.43,33.37
  Bottom 0.125: U$33.P$2 U$61.P$1 131.52,39.82 131.52,39.86 131.94,40.28 v133.56,40.28
N$83  (via drill 0.2)
  Top 0.125: v116.59,44.53 116.96,44.53 U$8.P$1 | U$7.P$15 v127.37,43.91
  Route2 0.125: v127.37,43.91 126.66,43.2 120.52,43.2 120.15,43.56 117.57,43.56 v116.59,44.53
  Bottom 0.125: v116.59,44.53 117.31,44.53 U$82.P$2
N$84  (via drill 0.3)
  Bottom 0.15: U$80.P$1 v114.99,45.58
N$85  (via drill 0.2)
  Top 0.125: U$37.P$1 116.95,40.2 v116.57,40.2 | 127.35,40.24 127.38,40.27 v127.38,40.9
  Top 0.15: 127.4,40.15 U$7.P$2 127.35,40.24 | U$37.P$1
  Route2 0.125: v116.57,40.2 117.22,40.2 119.05,42.03 125.33,42.03
  Route2 0.15: v127.38,40.9 127.02,41.41 125.33,41.44 125.33,42.03
  Bottom 0.125: U$79.P$2 116.57,40.49 v116.57,40.2
N$86  (via drill 0.3)
  Bottom 0.15: U$79.P$1 v114.99,41.26
N$89  (via drill 0.3)
  Bottom 0.15: U$78.P$1 v114.99,42.36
